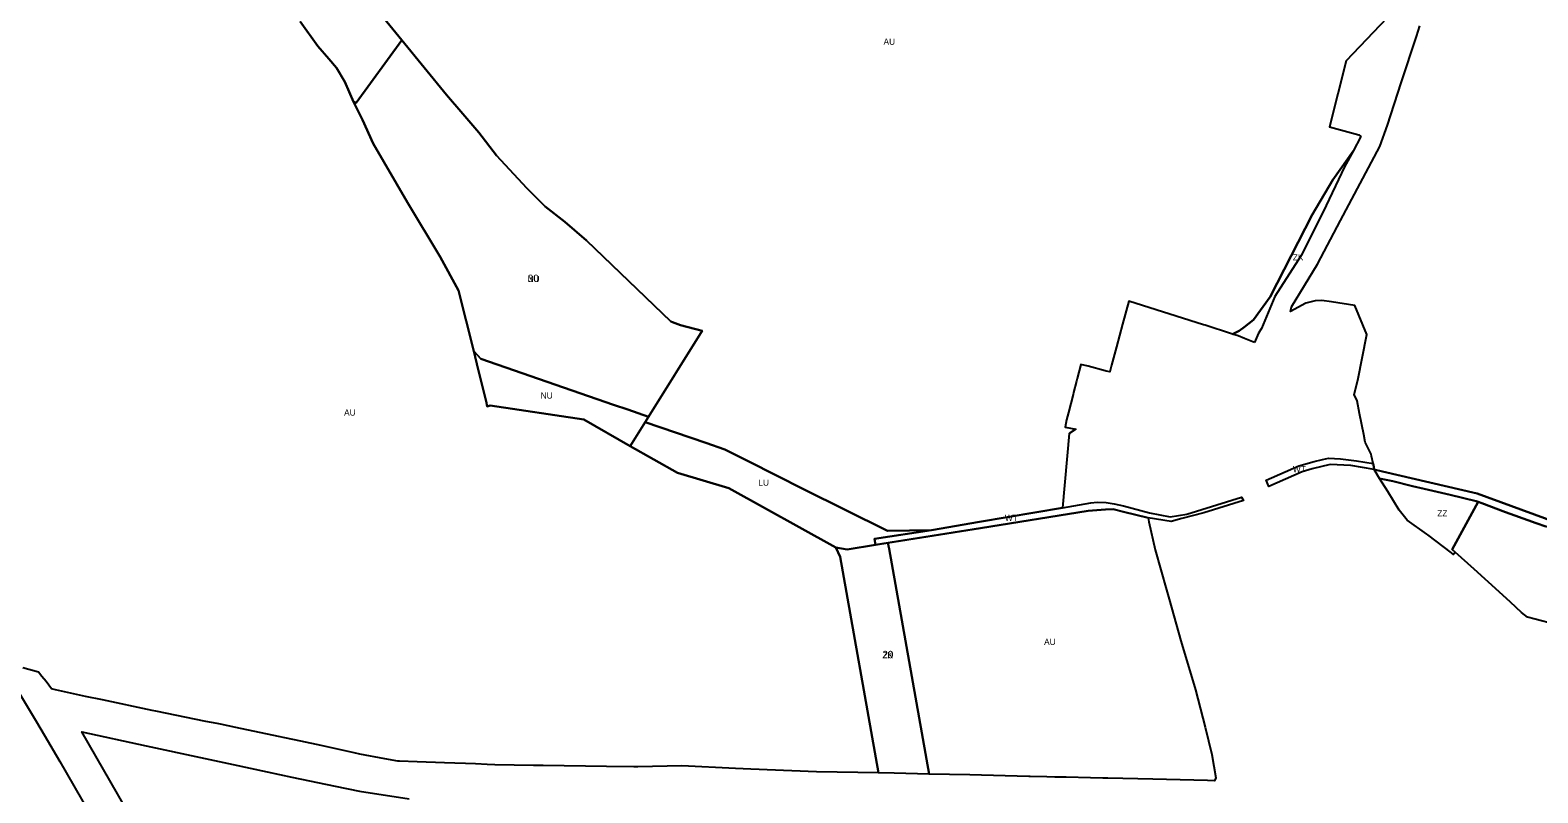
# Model space of a CAD drawing. Extents: x -541351 to -537540, y -1162694 to -1159725.
# Drawn here: x -539459 to -538243, y -1161316 to -1160701 of the extents above; entities that cross this region are included whole.
import ezdxf

# ---------------------------------------------------------------- set-up
doc = ezdxf.new("R2010")
doc.units = 0
for name, color, linetype in [('90640013', 7, 'Continuous'), ('90670013', 7, 'Continuous'), ('90710013', 7, 'Continuous'), ('90710023', 7, 'Continuous'), ('90730013', 7, 'Continuous'), ('90730023', 7, 'Continuous'), ('90750013', 7, 'Continuous'), ('90770013', 7, 'Continuous'), ('ID_navrh', 7, 'Continuous')]:
    doc.layers.add(name, color=color, linetype=linetype)

msp = doc.modelspace()

# ---------------------------------------------------------------- linework, layer by layer
at = {"layer": '90640013'}
for points in [[(-538402.37, -1161047.16), (-538389.53, -1161048.56), (-538376.1, -1161050.85), (-538375.54, -1161053.52), (-538375.11, -1161055.56), (-538394.11, -1161052.5), (-538410.51, -1161051.61), (-538425.13, -1161055.04), (-538433.26, -1161057.59), (-538460.08, -1161069.26), (-538462.33, -1161064.36), (-538435.93, -1161052.63), (-538423.48, -1161049.06), (-538416.92, -1161047.55), (-538411.91, -1161046.39)], [(-538375.11, -1161055.56), (-538368.36, -1161057.14), (-538292.2, -1161074.93), (-538121.13, -1161137.53), (-538123.8, -1161142.88), (-538145.25, -1161135.18), (-538166.87, -1161127.08), (-538180.71, -1161122.06), (-538194.34, -1161117.12), (-538209.76, -1161111.53), (-538221.89, -1161107.13), (-538236.85, -1161101.71), (-538244.47, -1161098.87), (-538261.65, -1161092.73), (-538269.37, -1161089.96), (-538288.24, -1161082.83), (-538291.28, -1161081.71), (-538292.78, -1161081.15), (-538313.99, -1161076.13), (-538334.92, -1161071.21), (-538344.15, -1161068.97), (-538360.05, -1161065.13), (-538370.98, -1161062.77)], [(-538598.6, -1161081.89), (-538591.21, -1161082.22), (-538584.7, -1161083.31), (-538577.37, -1161084.9), (-538556.35, -1161090.59), (-538539.71, -1161093.92), (-538526.14, -1161091.73), (-538482.08, -1161077.92), (-538480.58, -1161080.62), (-538512.52, -1161090.51), (-538530.38, -1161095.21), (-538538.92, -1161097.46), (-538557.43, -1161094.56), (-538577.33, -1161089.66), (-538585.6, -1161087.64), (-538591.79, -1161087.91), (-538605.83, -1161089), (-538692.62, -1161102.94), (-538777.25, -1161116.39), (-538778.08, -1161111.52), (-538732.03, -1161104.5), (-538693.5, -1161097.87), (-538626.44, -1161086.63), (-538603.66, -1161082.58)]]:
    msp.add_lwpolyline(points, close=True, dxfattribs=at)
at = {"layer": '90670013'}
msp.add_lwpolyline([(-538370.98, -1161062.77), (-538360.05, -1161065.13), (-538344.15, -1161068.97), (-538334.92, -1161071.21), (-538313.99, -1161076.13), (-538292.78, -1161081.15), (-538291.28, -1161081.71), (-538312.18, -1161120.2), (-538309.82, -1161122.33), (-538311.13, -1161124.22), (-538312.92, -1161122.85), (-538331.9, -1161108.41), (-538332.7, -1161107.83), (-538348.52, -1161096.5), (-538354.88, -1161088.4), (-538364.24, -1161073.5)], close=True, dxfattribs=at)
at = {"layer": '90710013'}
msp.add_lwpolyline([(-538471.55, -1160953.26), (-538479.72, -1160949.92), (-538484.94, -1160947.9), (-538489.27, -1160946.51), (-538483.94, -1160943.91), (-538479.98, -1160940.83), (-538472.49, -1160935.01), (-538458.97, -1160916.28), (-538425.21, -1160850.37), (-538408.52, -1160822.02), (-538392.23, -1160798.92), (-538399.17, -1160811.69), (-538416.18, -1160847.88), (-538434.13, -1160882.98), (-538455.22, -1160916.24), (-538465.91, -1160942.01), (-538468.45, -1160945.63)], close=True, dxfattribs=at)
at = {"layer": '90710023'}
msp.add_lwpolyline([(-539173.73, -1160691.8), (-539159.22, -1160709.51), (-539196.09, -1160759.86), (-539198.32, -1160759.07), (-539205.22, -1160742.97), (-539212.05, -1160731.79), (-539218.11, -1160724.6), (-539226.94, -1160714.26), (-539241.32, -1160694.3)], dxfattribs=at)
msp.add_lwpolyline([(-538762.23, -1161300.41), (-538775.002, -1161300.218), (-538805.75, -1161126.05), (-538809.39, -1161118.52), (-538800.13, -1161120.03), (-538777.25, -1161116.39), (-538767.229, -1161114.797), (-538766.35, -1161119.74), (-538734.05, -1161301.26)], close=True, dxfattribs=at)
at = {"layer": '90730013'}
msp.add_lwpolyline([(-539090.53, -1161004.95), (-539091.23, -1161000.54), (-539097.61, -1160975.07), (-539101.33, -1160960.2), (-539095.57, -1160966.53), (-539062.15, -1160978.04), (-538988.49, -1161003.42), (-538977.08, -1161007.35), (-538960.29, -1161013.08), (-538962.992, -1161017.416), (-538975.028, -1161036.731), (-539012.62, -1161015.43), (-539087.9, -1161004.04)], close=True, dxfattribs=at)
at = {"layer": '90730023'}
msp.add_lwpolyline([(-538988.49, -1161003.42), (-539062.15, -1160978.04), (-539095.57, -1160966.53), (-539101.33, -1160960.2), (-539113.58, -1160911.28), (-539128.35, -1160884.12), (-539154.76, -1160840.33), (-539182.33, -1160792.82), (-539190.9, -1160773.73), (-539198.32, -1160759.07), (-539196.09, -1160759.86), (-539159.22, -1160709.51), (-539123.11, -1160753.62), (-539110.17, -1160768.73), (-539097.29, -1160783.9), (-539083, -1160802.43), (-539058.38, -1160828.79), (-539056.08, -1160831.08), (-539043.56, -1160843.53), (-539027.86, -1160856), (-539010.44, -1160871.03), (-538942.34, -1160936.25), (-538940.95, -1160936.8), (-538934.54, -1160939.32), (-538917.2, -1160943.93), (-538960.29, -1161013.08), (-538977.08, -1161007.35)], close=True, dxfattribs=at)
at = {"layer": '90750013'}
for points in [[(-538359.69, -1160685.93), (-538397.64, -1160726.21), (-538411.31, -1160779.41), (-538387.55, -1160785.84), (-538385.81, -1160787.12), (-538392.23, -1160798.92), (-538408.52, -1160822.02), (-538425.21, -1160850.37), (-538458.97, -1160916.28), (-538472.49, -1160935.01), (-538479.98, -1160940.83), (-538483.94, -1160943.91), (-538489.27, -1160946.51), (-538490.32, -1160946.17), (-538511.5, -1160939.32), (-538512.84, -1160938.9), (-538573.04, -1160919.88), (-538578.05, -1160938.34), (-538582.96, -1160956.82), (-538586.89, -1160971.44), (-538588.385, -1160976.999), (-538588.385, -1160976.999), (-538591.31, -1160976.212), (-538591.31, -1160976.212), (-538592.03, -1160976.02), (-538605.68, -1160972.27), (-538611.81, -1160970.84), (-538614.7, -1160982.18), (-538615.29, -1160984.51), (-538617.58, -1160993.5), (-538618, -1160995.13), (-538621.69, -1161009.62), (-538623.346, -1161015.71), (-538624.464, -1161021.399), (-538624.464, -1161021.399), (-538615.86, -1161023.09), (-538621.2, -1161026.62), (-538626.44, -1161086.63), (-538693.5, -1161097.87), (-538732.03, -1161104.5), (-538767.73, -1161105.17), (-538835.45, -1161071.57), (-538879.44, -1161049.27), (-538898.78, -1161039.46), (-538914.19, -1161034.17), (-538962.992, -1161017.416), (-538960.29, -1161013.08), (-538917.2, -1160943.93), (-538934.54, -1160939.32), (-538940.95, -1160936.8), (-538942.34, -1160936.25), (-539010.44, -1160871.03), (-539027.86, -1160856), (-539043.56, -1160843.53), (-539056.08, -1160831.08), (-539058.38, -1160828.79), (-539083, -1160802.43), (-539097.29, -1160783.9), (-539110.17, -1160768.73), (-539123.11, -1160753.62), (-539159.22, -1160709.51), (-539173.73, -1160691.8)], [(-539241.32, -1160694.3), (-539226.94, -1160714.26), (-539218.11, -1160724.6), (-539212.05, -1160731.79), (-539205.22, -1160742.97), (-539198.32, -1160759.07), (-539190.9, -1160773.73), (-539182.33, -1160792.82), (-539154.76, -1160840.33), (-539128.35, -1160884.12), (-539113.58, -1160911.28), (-539101.33, -1160960.2), (-539097.61, -1160975.07), (-539091.23, -1161000.54), (-539090.53, -1161004.95), (-539087.9, -1161004.04), (-539012.62, -1161015.43), (-538975.028, -1161036.731), (-538936.84, -1161058.37), (-538895.58, -1161070.78), (-538809.39, -1161118.52), (-538805.75, -1161126.05), (-538775.002, -1161300.218), (-538824.88, -1161299.47), (-538844.86, -1161298.63), (-538877.93, -1161297.24), (-538890.19, -1161296.72), (-538933.47, -1161294.66), (-538968.85, -1161295.34), (-538971.53, -1161295.41), (-538972.25, -1161295.43), (-538994.31, -1161295.03), (-539045.37, -1161294.34), (-539053.1, -1161294.23), (-539084.18, -1161293.8), (-539090.47, -1161293.43), (-539099.9, -1161293.1), (-539108, -1161292.84), (-539116.49, -1161292.48), (-539124.88, -1161292.22), (-539146.97, -1161291.52), (-539161.16, -1161290.98), (-539162.36, -1161290.96), (-539173.01, -1161288.87), (-539193.16, -1161285.12), (-539197.72, -1161284.19), (-539224.32, -1161278.28), (-539240.79, -1161274.83), (-539253.51, -1161272.15), (-539258.85, -1161270.91), (-539293.08, -1161263.8), (-539305.49, -1161261.12), (-539308.15, -1161260.59), (-539317.28, -1161258.8), (-539357.66, -1161250.4), (-539360.48, -1161249.96), (-539400.77, -1161241.37), (-539414.3, -1161238.64), (-539438.49, -1161233.39), (-539441.79, -1161232.59), (-539446.12, -1161226.55), (-539449.58, -1161222.58), (-539452.22, -1161219.18), (-539464.98, -1161215.56)], [(-538121.13, -1161137.53), (-538292.2, -1161074.93), (-538368.36, -1161057.14), (-538375.11, -1161055.56), (-538375.54, -1161053.52), (-538376.1, -1161050.85), (-538377.363, -1161044.764), (-538377.69, -1161043.19), (-538382.38, -1161033.69), (-538383.46, -1161027.53), (-538386.99, -1161010.43), (-538388.91, -1161000.28), (-538391.26, -1160995.27), (-538388.39, -1160983.67), (-538381.11, -1160946.82), (-538390.72, -1160923.44), (-538409.56, -1160920.4), (-538417.35, -1160919.46), (-538422.65, -1160919.67), (-538430.33, -1160921.43), (-538442.66, -1160928.28), (-538441.72, -1160924.35), (-538431.35, -1160907.37), (-538420.84, -1160890.16), (-538402.43, -1160854.81), (-538370.7, -1160795.06), (-538364.45, -1160778.07), (-538353.36, -1160743.92), (-538341.15, -1160706.33), (-538338.41, -1160697.91)], [(-538228.93, -1161180.63), (-538245.22, -1161176.32), (-538251.46, -1161174.67), (-538256.27, -1161170.96), (-538265.17, -1161162.63), (-538274.43, -1161154.28), (-538294.53, -1161136.13), (-538309.82, -1161122.33), (-538312.18, -1161120.2), (-538291.28, -1161081.71), (-538288.24, -1161082.83), (-538269.37, -1161089.96), (-538261.65, -1161092.73), (-538244.47, -1161098.87), (-538236.85, -1161101.71)], [(-539468.39, -1161234.85), (-539453.999, -1161259.118), (-539447.73, -1161269.69), (-539434.98, -1161291.19), (-539405.14, -1161343.09), (-539392.4, -1161365.24), (-539396.15, -1161369.7), (-539442.69, -1161366.45), (-539490.23, -1161363.16)], [(-539382.245, -1161327.916), (-539417.292, -1161267.224), (-539417.292, -1161267.224), (-539365.38, -1161278.564), (-539321.669, -1161288.026), (-539295.249, -1161293.626), (-539267.896, -1161299.327), (-539248.033, -1161303.63), (-539213.032, -1161310.985), (-539193.318, -1161315.105), (-539153.268, -1161321.094)]]:
    msp.add_lwpolyline(points, dxfattribs=at)
msp.add_lwpolyline([(-538556.8, -1161097.89), (-538551.77, -1161120.48), (-538542.65, -1161152.77), (-538540.56, -1161160.19), (-538531.03, -1161193.7), (-538530.23, -1161196.53), (-538519.37, -1161233.31), (-538511.48, -1161263.37), (-538505.94, -1161285.46), (-538502.73, -1161304.19), (-538503.96, -1161306.59), (-538509.52, -1161306.46), (-538553.54, -1161305.46), (-538589.83, -1161304.64), (-538594.08, -1161304.54), (-538604.03, -1161304.32), (-538623.58, -1161303.88), (-538632.77, -1161303.67), (-538639.09, -1161303.52), (-538652.47, -1161303.22), (-538653.67, -1161303.19), (-538701.15, -1161301.97), (-538734.05, -1161301.26), (-538766.35, -1161119.74), (-538767.229, -1161114.797), (-538692.62, -1161102.94), (-538605.83, -1161089), (-538591.79, -1161087.91), (-538585.6, -1161087.64), (-538577.33, -1161089.66), (-538557.43, -1161094.56)], close=True, dxfattribs=at)
at = {"layer": '90770013'}
msp.add_lwpolyline([(-538962.992, -1161017.416), (-538914.19, -1161034.17), (-538898.78, -1161039.46), (-538879.44, -1161049.27), (-538835.45, -1161071.57), (-538767.73, -1161105.17), (-538732.03, -1161104.5), (-538778.08, -1161111.52), (-538777.25, -1161116.39), (-538800.13, -1161120.03), (-538809.39, -1161118.52), (-538895.58, -1161070.78), (-538936.84, -1161058.37), (-538975.028, -1161036.731)], close=True, dxfattribs=at)

# ---------------------------------------------------------------- texts
at = {"layer": '90640013'}
for rotation, p in [(0, (-538440.711, -1161057.825)), (360, (-538672.918, -1161097.155))]:
    msp.add_text('WT', height=5, rotation=rotation, dxfattribs=at).set_placement(p)
at = {"layer": '90670013'}
msp.add_text('ZZ', height=5, rotation=360, dxfattribs=at).set_placement((-538324.279, -1161093.495))
at = {"layer": '90710013'}
msp.add_text('ZK', height=5, rotation=0, dxfattribs=at).set_placement((-538440.75, -1160887.064))
at = {"layer": '90710023'}
msp.add_text('ZK', height=5, rotation=360, dxfattribs=at).set_placement((-538771.72, -1161207.889))
at = {"layer": '90730013'}
msp.add_text('NU', height=5, rotation=0, dxfattribs=at).set_placement((-539047.31, -1160998.466))
at = {"layer": '90730023'}
msp.add_text('NU', height=5, rotation=0, dxfattribs=at).set_placement((-539057.76, -1160904.48))
at = {"layer": '90750013'}
for p in [(-538770.787, -1160713.135), (-539205.826, -1161012.184), (-538641.32, -1161197.115)]:
    msp.add_text('AU', height=5, rotation=0, dxfattribs=at).set_placement(p)
at = {"layer": '90770013'}
msp.add_text('LU', height=5, rotation=0, dxfattribs=at).set_placement((-538871.743, -1161068.723))
at = {"layer": 'ID_navrh'}
for s, p in [('30', (-539057.76, -1160904.48)), ('29', (-538771.72, -1161207.889))]:
    msp.add_text(s, height=6, rotation=0, dxfattribs=at).set_placement(p)

doc.saveas('drawing.dxf')
